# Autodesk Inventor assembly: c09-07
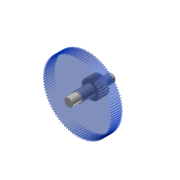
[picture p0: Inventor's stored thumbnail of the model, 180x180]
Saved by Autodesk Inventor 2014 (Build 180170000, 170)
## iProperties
Created: 2010-12
Part Number: c09-07
Document SubType Name: Assembly
Designer: Thom Tremblay
Author: Thom Tremblay
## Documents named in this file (4)
- C:\Inventor 2014 Essentials\Assemblies\Chapter 09\c09-07.iam
- C:\Inventor 2014 Essentials\Assemblies\Chapter 09\Design Accelerators\Shaft c09-07.iam
- C:\Inventor 2014 Essentials\Assemblies\Chapter 09\Design Accelerators\Cut Gear c09-04.iam
- C:\Inventor 2014 Essentials\Assemblies\Chapter 09\Design Accelerators\Spur Gear c09-02.iam
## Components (3 placed, 3 different names)
1. New Shaft:2 [sub-assembly] — Mate:1, Flush:1
2. Cut Gear:1 [sub-assembly]
3. Spur Gear1:1 [sub-assembly] — Mate:1, Flush:1
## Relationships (2: Mate 1, Flush 1)
- Mate:1: New Shaft:2 ↔ Spur Gear1:1
- Flush:1: New Shaft:2 ↔ Spur Gear1:1
